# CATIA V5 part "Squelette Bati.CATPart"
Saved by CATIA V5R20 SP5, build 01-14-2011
Part number: Squelette Bati
Publications: "Droite.1", "Droite.2", "Droite.3"
Bounding box of the stored display mesh (mm): x 0 to 0, y -250 to -50, z -70 to 30
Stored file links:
  U:\CFAO\Thinkmotion\Squelette Bati.CATPart
  U:\CFAO\Thinkmotion\Bras Articule.CATProduct
  U:\CFAO\Thinkmotion\Squelette general.CATPart
  U:\CFAO\Thinkmotion\Squelette Bielle L.CATPart
  U:\CFAO\Thinkmotion\Squelette Corps verin 1.CATPart
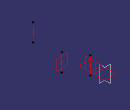
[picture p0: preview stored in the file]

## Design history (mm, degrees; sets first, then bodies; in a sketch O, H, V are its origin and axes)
Set1
  Line1: type Normal, RefPoint Point1, RefSkin Plane4, Start -30, End 30
  Line2: type Normal, RefPoint Point2, RefSkin Plane4, Start -30, End 30
  Line3: type Normal, RefPoint Point3, RefSkin Plane4, Start -30, End 30
  Plane1: type OffsetPt, RefPlane yz-plane, RefPoint Point1
  Plane2: type OffsetPt, RefPlane xy-plane, RefPoint Point1
  Plane3: type OffsetPt, RefPlane zx-plane, RefPoint Point2
Set2
  Plane4: linked copy from another document
  Point1 to Point3: linked copy from another document
Body1 (main body)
